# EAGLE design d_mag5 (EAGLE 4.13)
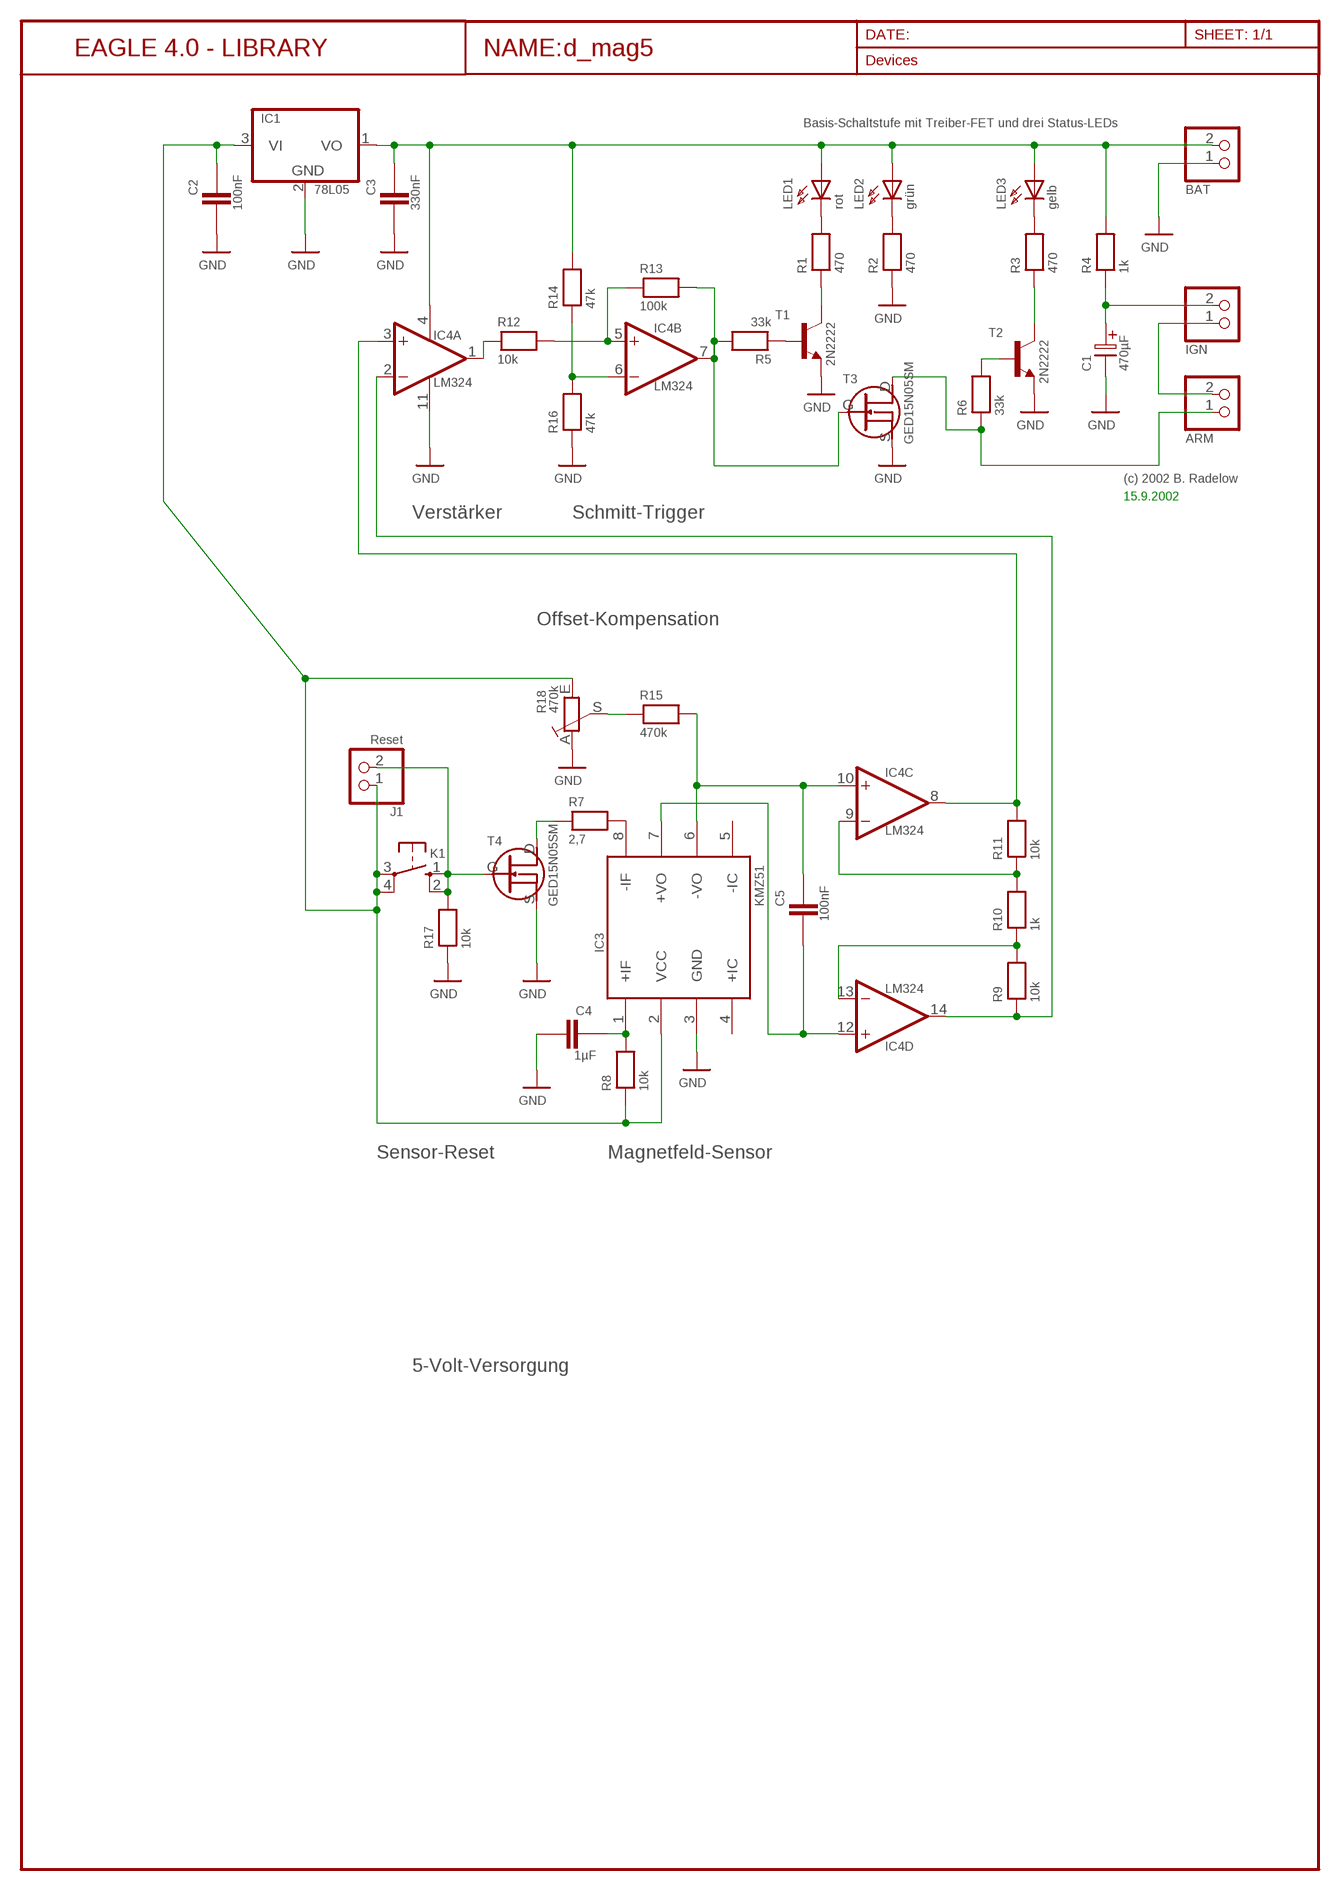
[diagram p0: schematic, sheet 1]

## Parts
ARM  PFOSTEN_1X2  [1X02]
BAT  PFOSTEN_1X2  [1X02]
C1  470µF  EC_470U  [E5-10,5]
C2  100nF  MKS2_10N-150N  [C5B2.5]
C3  330nF  MKS2_330N  [C5B3.5]
C4  1µF  MKS2_1000N  [C5B5]
C5  100nF  MKS2_10N-150N  [C5B2.5]
IC1  78L05  [TO92]
IC3  KMZ51  [SO8]
IC4  LM324  [DIL14]
IGN  PFOSTEN_1X2  [1X02]
J1  Reset  PFOSTEN_1X2  [1X02]
K1  TASTER_OMRON  [B3F-10XX]
LED1  rot  LED_3MM  [LED3MM]
LED2  grün  LED_3MM  [LED3MM]
LED3  gelb  LED_3MM  [LED3MM]
R1  470  R7,5  [0207/7]
R2  470  R7,5  [0207/7]
R3  470  R7,5  [0207/7]
R4  1k  R7,5  [0207/7]
R5  33k  R7,5  [0207/7]
R6  33k  R7,5  [0207/7]
R7  2,7  R7,5  [0207/7]
R8  10k  R7,5  [0207/7]
R9  10k  R7,5  [0207/7]
R10  1k  R7,5  [0207/7]
R11  10k  R7,5  [0207/7]
R12  10k  R7,5  [0207/7]
R13  100k  R7,5  [0207/7]
R14  47k  R7,5  [0207/7]
R15  470k  R7,5  [0207/7]
R16  47k  R7,5  [0207/7]
R17  10k  R7,5  [0207/7]
R18  470k  TRIM-S64Y  [S64Y]
T1  2N2222  [TO18]
T2  2N2222  [TO18]
T3  GED15N05SM  [TO252]
T4  GED15N05SM  [TO252]

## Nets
5VOLT: C2.1 IC1.3(VI) IC3.2(VCC) J1.1 K1.3(P) K1.4(P1) R8.1 R18.E(1E)
GND: BAT.1 C1.- C2.2 C3.2 C4.2 IC1.2(GND) IC3.3(GND) IC4.11(A:GND) R2.1 R16.1 R17.1 R18.A(1A) T1.1(E) T2.1(E) T3.S T4.S
N$1: ARM.2 IGN.1
N$2: LED2.K(C) R2.2
N$3: LED1.K(C) R1.2
N$4: LED3.K(C) R3.2
N$6: IC4.7(B:OUT) R5.2 R13.2 T3.G
N$8: ARM.1 R6.1 T3.D
N$11: C1.+ IGN.2 R4.1
N$12: R5.1 T1.2(B)
N$16: IC4.5(B:+IN) R12.2 R13.1
N$17: R1.1 T1.3(C)
N$18: IC4.6(B:-IN) R14.1 R16.2
N$19: IC4.9(C:-IN) R10.2 R11.1
N$20: IC4.13(D:-IN) R9.2 R10.1
N$21: IC4.2(A:-IN) IC4.14(D:OUT) R9.1
N$22: IC4.3(A:+IN) IC4.8(C:OUT) R11.2
N$23: C4.1 IC3.1(+IF) R8.2
N$24: C5.2 IC3.7(+VO) IC4.12(D:+IN)
N$25: R3.1 T2.3(C)
N$26: J1.2 K1.1(S) K1.2(S1) R17.2 T4.G
N$27: R6.2 T2.2(B)
N$28: C5.1 IC3.6(-VO) IC4.10(C:+IN) R15.2
N$29: R15.1 R18.S(1S)
N$30: IC3.8(-IF) R7.2
N$31: IC4.1(A:OUT) R12.1
N$37: R7.1 T4.D
V+: BAT.2 C3.1 IC1.1(VO) IC4.4(A:V+) LED1.A LED2.A LED3.A R4.2 R14.2
Unconnected: IC3.4(+IC) IC3.5(-IC)

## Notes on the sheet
- Basis-Schaltstufe mit Treiber-FET und drei Status-LEDs
- (c) 2002 B. Radelow
- 15.9.2002
- Verstärker | Schmitt-Trigger
- Offset-Kompensation
- Sensor-Reset | Magnetfeld-Sensor
- 5-Volt-Versorgung

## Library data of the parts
ARM BAT IGN J1 = _d_serie:PFOSTEN_1X2: Pfosten 2x1
C1 = _d_serie:EC_470U: 470µF 16V, Höhe 17mm
C2 C5 = _d_serie:MKS2_10N-150N: WIMA MKS2 Folienkondensator
C3 = _d_serie:MKS2_330N: WIMA MKS2 Folienkondensator 330nF
C4 = _d_serie:MKS2_1000N: WIMA MKS2 Folienkondensator 1µF
IC1 = _d_serie:78L05: Voltage Regulator 5V
IC3 = _d_serie:KMZ51: Magnetic Field Sensor
IC4 = _d_serie:LM324: LM324 - quad OpAmp
K1 = _d_serie:TASTER_OMRON: Taster, Omron
LED1-LED3 = _d_serie:LED_3MM
R1-R17 = _d_serie:R7,5: Widerstand 0,3 Watt liegend
R18 = _d_serie:TRIM-S64Y: Trimmer S64Y
T1 T2 = _d_serie:2N2222
T3 T4 = _d_serie:GED15N05SM: N-Channel Power-FET

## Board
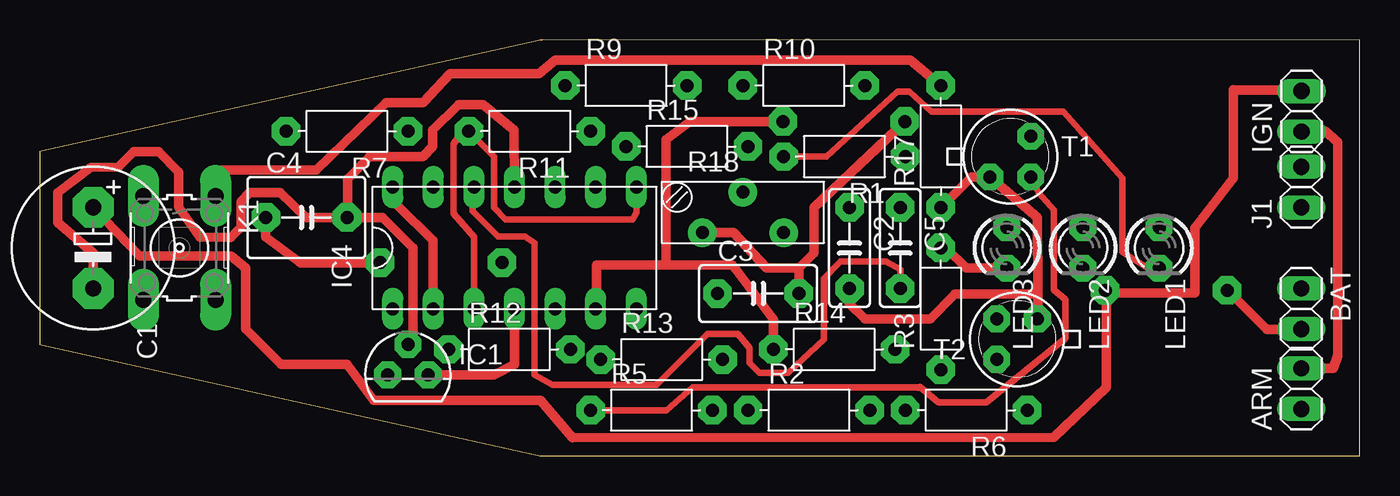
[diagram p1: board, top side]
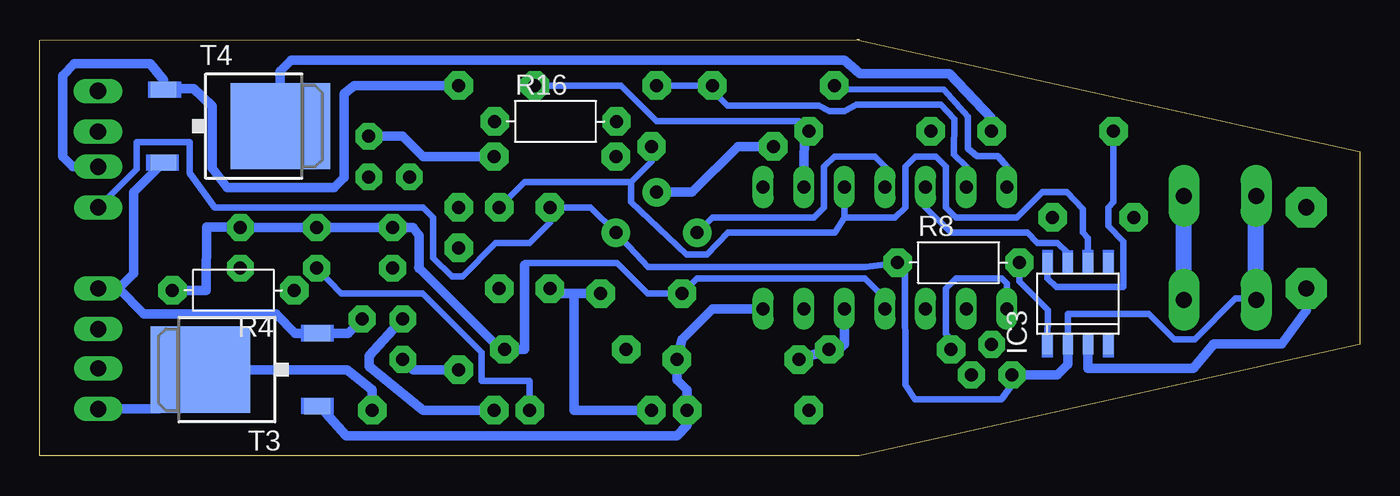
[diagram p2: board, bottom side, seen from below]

Size 82.54 x 26.04 mm. Coordinates in mm from the lower left corner, seen from the top.
Outline: 31.44,26.04 82.54,26.03 82.54,0 31.27,0 0,6.99 0,19.04 31.44,26.04
Outline: 31.27,26.04 31.44,26.04
Copper layers (1*16): Top 0.035mm / dielectric 1.5mm / Bottom 0.035mm
Design rules "default": minimum track width 10mil, minimum drill 24mil, track to track 8mil, track to pad 8mil, pad to pad 8mil, via to via 8mil, smd to smd 8mil, copper to edge 40mil, drill to drill 8mil, minimum pad ring 10mil, minimum via ring 8mil, stop-mask expansion 4mil, vias tented up to drill 0mil, thermal gap 10mil

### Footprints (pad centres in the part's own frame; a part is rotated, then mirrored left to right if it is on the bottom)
1X02 = drill 1.016 long: 1 -1.27,0; 2 1.27,0
E5-10,5 = drill 1.016 pad 2.54 round: + -2.54,0 | drill 1.016 pad 2.54 octagon: - 2.54,0
C5B2.5 = drill 0.813 pad 1.778 octagon: 1 -2.54,0; 2 2.54,0
C5B3.5 = drill 0.813 pad 1.778 octagon: 1 -2.54,0; 2 2.54,0
C5B5 = drill 0.813 pad 1.778 octagon: 1 -2.54,0; 2 2.54,0
TO92 = drill 0.813 pad 1.676 octagon: 1 1.27,0; 2 0,1.905; 3 -1.27,0
SO8 = smd 0.635 x 1.27: 1 -1.905,-2.54; 2 -0.635,-2.54; 3 0.635,-2.54; 4 1.905,-2.54; 5 1.905,2.54; 6 0.635,2.54; 7 -0.635,2.54; 8 -1.905,2.54
DIL14 = drill 0.813 long: 1 -7.62,-3.81; 2 -5.08,-3.81; 3 -2.54,-3.81; 4 0,-3.81; 5 2.54,-3.81; 6 5.08,-3.81; 7 7.62,-3.81; 8 7.62,3.81; 9 5.08,3.81; 10 2.54,3.81; 11 0,3.81; 12 -2.54,3.81; 13 -5.08,3.81; 14 -7.62,3.81
B3F-10XX = drill 1.016 pad 1.93 long: 1 -3.251,2.261; 2 3.251,2.261; 3 -3.251,-2.261; 4 3.251,-2.261
LED3MM = drill 0.813 pad 1.676 octagon: A -1.27,0; K 1.27,0
0207/7 = drill 0.813 pad 1.778 octagon: 1 -3.81,0; 2 3.81,0
S64Y = drill 0.813 pad 1.778 round: A -2.54,-1.27; E 2.54,-1.27; S 0,1.27
TO18 = drill 0.813 pad 1.676 octagon: 1 -1.27,-1.27; 2 1.27,-1.27; 3 1.27,1.27
TO252 = smd 5.4 x 6.2: D 0,1.23 | smd 1 x 1.6: G -2.28,-6.07; S 2.28,-6.07

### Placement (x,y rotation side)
ARM  78.89,4.21 90 top
BAT  78.89,9.21 270 top
C1  3.33,13.02 270 top
C2  50.64,13.02 270 top
C3  44.92,10.16 0 top
C4  16.66,14.92 0 top
C5  53.81,13.02 270 top
IC1  23.01,5.08 0 top
IC3  17.61,9.53 0 bottom
IC4  29.68,13.02 0 top
IGN  78.91,21.57 90 top
J1  78.89,16.83 90 top
K1  8.72,13.02 270 top
LED1  70,13.02 270 top
LED2  65.24,13.02 270 top
LED3  60.48,13.02 270 top
R1  50.32,18.73 180 top
R2  48.09,2.86 0 top
R3  56.35,9.21 90 top
R4  70.44,10.36 180 bottom
R5  38.25,2.86 0 top
R6  57.94,2.86 180 top
R7  19.2,20.32 180 top
R8  25.09,12.1 0 bottom
R9  36.66,23.18 0 top
R10  47.78,23.18 0 top
R11  30.63,20.32 180 top
R12  29.36,6.67 0 top
R13  38.89,6.03 0 top
R14  49.68,6.67 0 top
R15  40.48,19.37 0 top
R16  50.29,20.94 0 bottom
R17  56.35,19.37 90 top
R18  43.97,15.24 0 top
T1  60.7,18.73 0 top
T2  61.11,7.3 180 top
T3  71.27,5.4 90 bottom
T4  68.73,20.64 270 bottom

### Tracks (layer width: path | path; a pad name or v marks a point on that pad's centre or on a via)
5VOLT  (via drill 0.6)
  Top 0.406: v28.95,12.06 R8.1 v28.89,12.07
  Bottom 0.406: v28.95,12.06 30.91,11.82 44.52,11.83 R18.E 48.09,15.56 C2.1 50.64,14.61 51.9,13.34 54.04,13.34 56.1,11.23 56.75,11.22 57.94,12.38 57.94,14.92 58.57,15.56 71.62,15.56 73.18,17.69 73.18,19.65 76.49,19.65 76.49,17.94 J1.1 | 6.48,16.35 K1.3 | v28.89,12.07 28.42,11.44 28.41,4.44 27.81,3.54 22.42,3.54 21.74,4.44 IC1.3 21.42,5.08 | IC3.2 18.25,5.72 18.24,5.72 | 18.24,7.02 18.25,8.89 13.17,8.89 11.58,7.3 10.31,7.3 7.77,9.84 6.5,9.84 | 6.46,10.83 6.5,10.79 6.46,11.07 6.46,10.83
  Bottom 0.61: K1.4 6.46,10.83 | IC1.3 21.42,5.08 18.88,5.08 18.25,5.72 | 18.24,7.02 18.24,5.72 | 6.5,10.79 6.5,9.84
  Bottom 1.016: 6.5,10.79 6.48,16.35
GND  (via drill 0.6)
  Top 0.406: 21.42,14.92 19.23,14.96
  Top 0.61: 47.46,11.75 45.43,11.75 43.37,13.97 R18.A | 19.23,14.96 19.23,17.32 20.63,18.73 23.97,18.73 24.57,19.37 24.57,20.39 26.19,21.97 27.72,21.99 29.64,20.39 IC4.11 | R17.1 58.26,17.46 T1.1 62.38,14.92 62.41,10.13 | 62.41,10.13 T2.1 | C2.2 50.64,9.53 51.59,8.57 55.71,8.57 57.22,10.13 62.41,10.13 | v54.09,20.91 48.41,15.56 48.41,12.7 47.46,11.75 | 47.46,11.75 C3.2 | IC1.2 23.33,7.3 23.33,13.02 21.42,14.92 C4.2 16.66,14.92 15.01,16.48 13.11,16.48 12.6,15.91 12.6,14.32 11.93,13.68 9.99,13.7 8.69,15.58 8.69,17.78 7.44,19.03 5.87,19.03 4.9,18.06 3.17,18.06 1.12,16.49 1.12,14.61 3.33,12.7 C1.-
  Bottom 0.406: 74.82,18.36 T4.S | v54.09,20.91 R16.1 | R18.A 40.47,14.92 34.12,14.92 33.49,15.56 33.49,18.1 32.86,18.73 30.31,18.73 29.68,18.1 IC4.11
  Bottom 0.61: T2.1 63.28,7.68 T3.S 66.57,7.68 67.78,8.89 76.03,8.89 77.62,10.48 | 77.62,10.48 BAT.1 | 77.62,10.48 76.67,11.43 76.67,16.51 74.82,18.36 | 49.14,10.17 49.13,2.86 R2.1 | C1.- 3.33,9.11 4.87,7.01 9.12,7.01 10.39,5.48 16.99,5.48 IC3.3 | 49.23,10.16 49.25,10.14 49.14,10.17 | C3.2 49.23,10.16 | 49.23,10.16 49.23,10.15 | 50.09,10.16 50.7,10.48 C2.2 | 49.14,10.17 50.09,10.16 | 50.09,10.16 49.15,10.16
N$1
  Top 0.406: IGN.1 78.91,20.37 78.89,20.4 78.93,20.33
  Top 0.61: ARM.2 80.88,5.48 81.16,6.28 81.16,19.64 80.4,20.33 78.93,20.33
N$2
  Bottom 0.406: LED2.K 63.7,10.18 58.61,10.17 54.92,6.47 54.92,4.69 51.9,4.69 R2.2
N$3
  Top 0.406: R1.2 49.18,18.73 53.63,22.81 54.38,22.81 55.76,21.55 64.01,21.55 67.71,17.39 67.71,12.75 69.32,11.72 70.03,11.72 | 70.03,11.72 70.2,11.72 | 70.03,11.72 LED1.K
N$4
  Top 0.61: R3.2 56.67,13.02 57.94,11.75 LED3.K
N$5  (via drill 0.6 pad 2.54)
  other vias: 3.33,15.57
N$6
  Bottom 0.406: 64.66,2.71 T3.G
  Bottom 0.61: 64.66,2.71 63.37,1.27 42.7,1.27 42.06,1.9 R5.2 42.06,4.13 42.7,4.76 R13.2 42.38,7.3 40.47,9.21 IC4.7
N$7  (via drill 0.6 pad 2.54)
  other vias: 3.32,10.47
N$8
  Bottom 0.406: 75.08,2.94 72.54,5.4 T3.D
  Bottom 0.61: 75.08,2.94 ARM.1 | R6.1 61.75,4.13 63.32,5.4 72.54,5.4
N$11  (via drill 0.6)
  Top 0.406: 79.12,22.89 78.96,22.89 IGN.2 | 74.63,22.92 74.79,22.89
  Top 0.61: C1.+ 6.23,12.52 11.95,12.52 12.85,11.75 12.85,7.94 15.08,5.72 19.2,5.72 20.88,3.47 31.31,3.47 33.31,1.15 63.43,1.15 66.69,4.3 66.69,10.19 | 66.69,10.19 72.22,10.19 72.22,14.26 74.63,17.39 74.63,22.92 | 66.69,10.19 R4.1 | 74.79,22.89 78.96,22.89
  Bottom 0.406: v66.64,10.35 R4.1 66.68,10.33
N$12
  Top 0.406: R5.1 39.19,2.86 40.81,4.29 54.79,4.29 54.89,4.3 55.05,4.31 | 55.05,4.31 56.19,3.36 59.21,3.36 64.13,7.35 64.13,9.78 63.42,10.39 63.42,15.39 62.49,16.46 T1.2 | 55.05,4.31 54.95,4.25
N$16
  Bottom 0.406: R13.1 34.82,6.14 | R12.2 34.01,6.4
  Bottom 0.61: R13.1 R12.2 32.54,6.67 32.22,6.98 IC4.5 | 34.01,6.4 34.82,6.14
N$17
  Bottom 0.61: T1.3 59.84,20 58.57,18.73 R1.1
N$18
  Top 0.406: 34.8,9.13 34.8,9.21 IC4.6 | 43.29,11.94 43.44,11.78
  Top 0.61: R16.2 40.66,20.94 39.15,19.81 39.15,11.95 | 39.15,11.95 34.8,11.95 34.8,9.21 | R14.1 45.88,8.53 43.44,11.78 | 39.15,11.95 41.18,11.94 43.29,11.94
  Bottom 0.406: R16.2 46.5,20.93
N$19
  Bottom 0.406: R10.2 46.19,23.18 43.97,20.95 35.08,20.95 R11.1
  Bottom 0.61: R11.1 34.73,19.84 34.76,18.42 IC4.9
N$20
  Bottom 0.406: R10.1 R9.2 40.79,23.18 39.52,21.91 33.81,21.91 33.14,21.59 32.21,21.59 31.47,21.98 26.17,21.98 25.34,21.07 25.38,18.85 24.6,18.1 IC4.13
N$21
  Top 0.61: IC4.14 22.35,15.69 24.58,13.48 IC4.2
  Bottom 0.406: IC4.14 22.06,18.1 22.63,18.78 23.94,18.78 24.48,19.23 24.49,21.22 26.01,22.93 32.28,22.96 R9.1
N$22
  Top 0.406: IC4.3 27.14,13.71 25.89,15.16 25.89,19.55 26.51,20.32 R11.2 28.41,18.73 28.41,15.56 29.12,14.81 37.06,14.81 37.3,15.24 IC4.8
N$23  (via drill 0.6)
  Top 0.406: v21.27,12.08 R8.2
  Top 0.61: C4.1 14.12,13.72 16.32,12.07 v21.3,12.06
  Bottom 0.406: R8.2 v21.3,12.06 | IC3.1 19.5,9.13 21.28,10.93 v21.27,12.08
N$24
  Top 0.406: IC4.12 27.06,15.33 28.65,13.74 30.35,13.74 30.95,13.34 30.95,5.08 32.06,4.44 38.57,4.44 41.75,7.62 43.65,7.62 44.38,6.77 44.38,5.83 45.01,5.19 46.79,5.19 49.05,7.3 49.05,11.11 50.08,12.17 52.91,12.16 53.81,11.67 C5.2
  Bottom 0.406: IC3.7 18.25,12.7 18.88,13.34 20.15,13.34 20.79,13.97 25.55,13.97 27.14,15.56 IC4.12
N$25
  Bottom 0.61: T2.3 59.21,5.4 R3.1
N$26
  Top 0.406: 10.99,16.83 10.95,16.19
  Top 0.61: R17.2 54.44,24.76 32.22,24.76 31.21,23.92 25.66,23.92 23.96,22.11 21.64,22.12 17.29,17.88 10.94,17.88 10.99,16.83 K1.1
  Bottom 0.406: 74.8,23.53 T4.G | 11.02,16.27 10.97,16.19 11.01,16.33 K1.1 11.02,16.27
  Bottom 0.61: 74.8,23.53 75.64,24.56 80.4,24.56 81.12,23.81 81.12,18.73 80.48,18.1 J1.2 | R17.2 62.89,23.18 63.5,22.69 63.5,17.43 64.15,16.8 70.82,16.8 71.76,18.03 71.76,21.9 72.91,22.98 75.04,22.97 75.04,22.92 | 75.13,23 75.04,22.92 | 75.04,22.92 T4.G
  Bottom 1.016: K1.2 K1.1
N$27
  Bottom 0.61: R6.2 58.57,2.86 61.94,5.61 61.94,6.25 T2.2
N$28
  Bottom 0.406: 32.22,14.92 32.82,13.99 39.49,13.99 40.82,12.6 42.09,12.6 45.55,15.88 45.55,17.15 | 32.22,14.92 IC4.10 | 45.55,17.15 44.29,18.42 R15.2 | C5.1 52.22,17.15 45.55,17.15 | IC3.6 16.98,13.65 17.3,13.97 17.3,15.46 18.3,16.51 19.84,16.51 21.42,14.92 25.24,14.92 25.87,15.56 25.87,18.1 26.51,18.73 27.77,18.73 28.41,18.1 28.41,15.56 29.04,14.92 32.22,14.92
N$29
  Bottom 0.61: R18.S 41.75,16.51 38.89,19.37 R15.1
N$30
  Bottom 0.406: IC3.8 19.52,11.11 18.96,10.57 14.76,10.57 14.76,13.42 15.7,14.39 15.71,15.56 15.39,15.88 R7.2
N$31
  Bottom 0.406: R12.1 25.55,7.3 25.87,7.62 25.87,10.48 25.24,11.11 22.38,11.11 22.06,10.79 IC4.1
N$37
  Bottom 0.61: T4.D 67.5,24.09 66.83,24.76 32.22,24.76 31.23,23.93 25.65,23.93 23.01,21.14 R7.1
V+  (via drill 0.6)
  Top 0.406: v74.23,10.34 R4.2
  Top 0.61: v74.3,10.36 76.75,7.91 77.89,7.91 BAT.2 | IC1.1 28.41,5.08 29.68,5.72 IC4.4
  Bottom 0.406: 52.29,8.66 52.2,11.96 52.2,12.06 46.43,12.06 44.53,10.16 C3.1 41.43,11.11 30.95,11.11 29.68,9.84 IC4.4 | R4.2 v74.3,10.36 | 69.99,14.29 | LED1.A 69.99,14.29 | 69.99,14.29 69.99,14.31
  Bottom 0.61: LED1.A LED2.A LED3.A 59.21,14.29 58.84,13.79 58.84,11.78 | 58.84,11.78 58.84,11.72 | 52.23,11.96 | 52.2,11.96 52.23,11.96 | R14.2 52.23,6.67 52.23,11.96 | 52.23,11.96 52.23,6.66 53.73,6.66 58.85,11.78 58.84,11.78 | v74.23,10.34 72.16,10.34 72.13,14.31 69.99,14.31
(copper drawn outside any net)
  shapes: Bottom area x10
